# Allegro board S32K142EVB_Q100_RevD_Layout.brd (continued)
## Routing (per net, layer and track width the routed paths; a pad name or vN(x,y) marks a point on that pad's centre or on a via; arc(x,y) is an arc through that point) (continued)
SDA_SWD_EN_B_R: length 3.1
  TOP w0.16: R49.1 37.17,38.52 v1(37.17,38.54) 37.17,38.54 37.17,38.55 36.6,39.13 R42.2 35.78,39.15 35.63,39.3 U9.1
SDA_SWD_EN_R: length 3.7
  TOP w0.16: U10.5 R52.2 31.03,38.13 R51.1 32.03,38.13 R47.2
SDA_SWD_OE: length 2.5
  TOP w0.16: U9.4 34.05,40 33.9,40.15 R35.1 R38.1
SDA_SWD_OE_B: length 19.5
  TOP w0.16: v1(35.85,40.73) 35.59,41 35.59,41.44 R32.2 ; v1(25.27,37.82) 24.3,37.82 23.87,37.39 21.49,37.39 U8.20
  BOTTOM w0.16: v1(25.27,37.82) 26.89,36.19 32.87,36.19 35.12,38.44 35.12,38.89 35.42,39.19 35.42,40.3 v1(35.85,40.73)
SDA_SWD_OE_B_R: length 3.5
  TOP w0.16: U9.3 35.64,40 35.79,40.15 R39.1 R32.1 v1(36.6,42.23)
SDA_SWD_OE_R: length 3.7
  TOP w0.16: U7.5 30.4,41.16 30.43,41.19 R30.2 R31.1 31.99,41.16 R35.2
SDA_USB_CONN_DN: length 13.3
  TOP w0.145: J7.2 4.65,43.37 4.83,43.55 7.56,43.55 7.94,43.17 7.94,43.11 ; 7.94,43.11 8.34,43.52 12.57,43.52 13.41,44.37 15.33,44.37 15.73,43.97 R25.1 ; 7.94,43.11 D19.2
SDA_USB_CONN_DP: length 13.6
  TOP w0.145: 7.92,44.3 7.46,43.85 4.85,43.85 4.67,44.02 J7.3 ; 7.92,44.3 D18.2 ; 7.92,44.3 7.92,44.29 8.39,43.82 12.44,43.82 13.29,44.66 15.45,44.66 15.94,44.18 R21.1
SDA_USB_DN: length 2.1
  TOP w0.145: U8.4 17.65,41.94 17.65,42.08 17.08,42.65 R25.2
SDA_USB_DP: length 2.1
  TOP w0.145: U8.3 17.99,42.31 17.84,42.31 17.29,42.86 17.29,42.86 17.25,42.9 R21.2
SDA_USB_P5V_SENSE: length 4.6
  TOP w0.16: v1(23.98,45.22) R14.2 22.79,44.04 22.79,44.04 R20.1 21.47,42.72 U8.30
SDA_USBSHIELD: length 9.3
  TOP w0.16: 6.21,40.76 L2.1 5.62,40.27
  TOP w1.016: J7.9 J7.8 J7.10
SDA_VOUT33: length 5.9
  TOP w0.254: C9.1 15.71,41.97 16.91,41.97 U8.5
  TOP w0.508: C9.1 15.18,41.44 13.8,41.44 13.55,41.69 R627.1
SDA_XTAL: length 5.3
  TOP w0.16: U8.18 20.95,36.51 22.61,36.51 C20.1 23.41,35.71 23.41,35.3 Y1.1
SW1_RST_B: length 14.2
  TOP w0.16: C1.1 v1(10.7,53.19) 11.15,53.63 SW5.2 SW5.4
  L3_MIX w0.16: v1(10.7,53.19) 10.7,51.79 J104.2
SWD_CLK_TGTMCU_BUF: length 1.5
  TOP w0.16: U10.4 29.34,37.23 29.55,37.01 R626.2
SWD_DIO_TGTMCU_BUF: length 11.6
  TOP w0.16: U7.4 v1(30.02,40.66) ; R625.2 31,47.92 v1(30.44,47.35) U2.2
  BOTTOM w0.16: v1(30.02,40.66) 30.78,40.66 32.05,41.94 32.05,45.74 v1(30.44,47.35)
TC_EXTAL_TP: length 2.2
  TOP w0.16: TP11.1 15.72,37.97 16.09,38.34 16.39,38.34 U8.10
TC_SDA_USB_ID_TP: length 2.2
  TOP w0.16: J7.4 5.88,44.67 TP6.1
TC_XTAL_TP: length 3
  TOP w0.16: U8.9 16.19,38.85 15.83,38.85 TP10.1
TP_2102_A: length 2.5
  TOP w0.16: U1.3 R607.2 7.71,53.43 v1(7.74,53.46)
TP_2102_B: length 1.6
  TOP w0.203: U1.6 7.31,49.22 7.2,49.11 R608.2
UART1_RX_TGTMCU_BUF: length 4.9
  TOP w0.16: R24.1 v1(32.98,43.47) 32.66,43.8 30.44,43.8 30.29,43.94 U4.4
UART1_RX_TGTMCU_R: length 8.8
  TOP w0.16: U8.25 22.89,40.6 23.67,40.6 23.84,40.42 25.39,40.42 v1(25.86,40.9) ; v1(27.02,43.73) 27.83,43.73 28.04,43.94 U4.3
  BOTTOM w0.16: v1(27.02,43.73) 27.02,42.06 v1(25.86,40.9)
UART1_TX_TGTMCU_BUF: length 3.2
  TOP w0.16: R18.1 32.44,46.65 32.26,46.83 v1(31.84,46.83) U2.1
UART1_TX_TGTMCU_R: length 10.9
  TOP w0.16: v1(27.12,44.65) 27.65,45.18 27.65,47.12 27.88,47.35 U2.6 ; U8.24 v1(23.29,40.08)
  BOTTOM w0.16: v1(27.12,44.65) 26.34,43.87 26.34,43.14 v1(23.29,40.08)
UART_RX: length 53.1
  TOP w0.16: R161.1 v1(84.29,44.36) ; R24.2 v1(34.89,44.49)
  BOTTOM w0.16: v1(34.89,44.49) 48.98,44.49 51.02,46.52 51.05,46.52 51.13,46.6 72.78,46.6 73.11,46.27 82.38,46.27 v1(84.29,44.36)
UART_TX: length 55.6
  TOP w0.16: R162.1 v1(85.43,44.36) ; R18.2 v1(34.51,46.65)
  BOTTOM w0.16: v1(34.51,46.65) 35.27,46.65 36.86,45.06 48.67,45.06 50.38,46.77 50.79,46.77 50.88,46.86 50.91,46.86 50.99,46.94 72.92,46.94 73.21,46.65 83.78,46.65 85.43,45 v1(85.43,44.36)
V_TGTMCU: length 15.8
  TOP w0.203: v1(8.22,47.41) R608.1 8.22,49.11 8.11,49.22 U1.8
  TOP w0.254: U10.6 29.8,38.62 29.88,38.7 v1(30.05,38.7) ; v1(30.04,41.89) 29.81,41.66 U7.6 ; U2.8 29.05,46.31 v1(29.34,46.01) U4.6 ; 2.99,49.63 C4.1 ; 2.98,50.98 R2.2 2.47,50.47 ; 3.5,51.1 R4.1 2.99,50.59 ; 1.49,50.47 C2.1 0.98,50.98 ; C8.1 v1(30.09,42.77)
  TOP w0.762: v1(38.48,42.57) v1(39.52,42.57) 39.52,39.41 38.86,38.76 SH1.1
  vias: v1(1.85,50.09) v1(2.77,50.09)
VSUP: length 34.6
  TOP w0.254: U19.14 v1(15.66,18.74)
  TOP w0.381: TP508.1 35.35,14.56 ; TP508.1 35.35,15.49 ; TP508.1 34.42,14.56 ; TP508.1 34.89,14.45 ; TP508.1 35.46,15.02 ; TP508.1 34.31,15.02 ; TP508.1 34.89,15.6 ; TP508.1 34.42,15.49 ; 34.47,18.33 C47.1 ; C47.1 34.59,18.16 ; C47.1 34.51,18.58 ; C47.1 34.77,18.04 ; C47.1 35.44,18.16 ; C47.1 35.01,18.07 ; 32.08,16.87 Q1.2 ; Q1.2 32.08,17.86 ; Q1.2 32.88,17.37 ; C546.1 36.67,18.58 ; C546.1 36.16,18.07 ; C546.1 36.58,18.16 ; C546.1 35.91,18.04 ; C546.1 35.73,18.16 ; C546.1 35.61,18.33 ; Q1.1 32.88,16.1 ; Q1.1 32.08,15.6 ; Q1.1 32.08,16.59 ; 32.08,18.14 Q1.3 32.88,18.64 ; 32.26,11.98 D9.C ; D9.C 33.15,10.73 ; D9.C 33.15,13.22 ; D9.C 34.04,11.98 ; 37.11,10.96 C128.1 ; C128.1 39.08,11.98 ; C128.1 35.14,11.98 ; C128.1 37.11,12.99
  TOP w0.61: D6.A 20.63,23.5 21.29,24.16 U21.7
  TOP w0.635: D6.A v1(17.99,23.5) ; R537.1 10.42,9.04 11.06,9.67 v1(11.06,9.95)
  vias: v1(32.09,13.88) v1(34.63,11.98)
VTRG_EN: length 4.6
  TOP w0.16: R69.2 R68.1 R70.2 v1(9.98,31.94) U11.3
VTRG_FAULT_B: length 16.3
  TOP w0.16: U11.4 11.22,35.53 R60.2 v1(12.67,35.53) ; v1(20.38,43.64) 20.38,43.04 U8.32
  BOTTOM w0.16: v1(12.67,35.53) 14.62,37.48 14.62,39.3 15.71,40.39 17.59,40.39 20.38,43.18 v1(20.38,43.64)
N20187731: length 2.1
  TOP w0.16: D11.A3 119.42,15.43 119.34,15.51 R95.1
N20187747: length 2.1
  TOP w0.16: R96.1 121.5,15.45 121.52,15.43 D11.A2
N20224636: length 9.7
  TOP w0.16: R597.1 C5.1 119.78,46.27 119.81,46.24 R13.2 119.08,44.49 117.82,44.49 TP5.1
N20296072: length 11
  TOP w0.16: TP532.1 122.39,38.82 122.43,38.78 SW2.1 SW2.3 R44.1 119.72,32.55 R596.1
N20296289: length 10.8
  TOP w0.16: SW3.1 SW3.3 ; SW3.1 122.43,26.96 122.39,27 TP531.1 ; SW3.1 R74.1 119.71,25.82 R595.1
N20296614: length 2.1
  TOP w0.16: R97.1 123.66,15.47 123.62,15.43 D11.A1
N20337791: length 7.2
  TOP w0.16: R662.2 R122.2 70.37,39.61 U35.98
N20337946: length 51.4
  TOP w0.16: R165.2 v1(82.99,44.37) ; v1(73.49,14.01) 73.49,14.85 R166.2
  L3_MIX w0.16: J5.3 73.11,8.17 73.11,12.61 73.49,12.99 v1(73.49,14.01) ; v1(82.99,44.37) 82.32,43.71 82.32,35.18 83.03,34.48 83.03,16.55 v1(82,15.53)
  BOTTOM w0.16: v1(82,15.53) 81.88,15.66 75.15,15.66 v1(73.49,14.01)
N20338052: length 6.6
  TOP w0.16: U35.92 73.37,37.88 72.86,38.39 72.86,39.41 73.25,39.79 R123.2 R663.2
N20338949: length 53.8
  TOP w0.16: v1(71.34,14.01) 71.97,14.65 R168.2 ; J5.1 v1(71.69,5.12) ; R167.2 v1(81.31,44.27)
  L3_MIX w0.16: v1(71.34,14.01) 71.34,12.96 71.25,12.88 71.25,6.86 71.69,6.43 v1(71.69,5.12) ; v1(81.31,44.27) 81.37,44.21 81.37,41.69 81.64,41.42 81.64,34.9 82.32,34.23 82.32,18.76 80.86,17.31 v1(80.86,15.15)
  BOTTOM w0.16: v1(80.86,15.15) 80.78,15.23 75.61,15.23 73.87,13.5 71.85,13.5 v1(71.34,14.01)
N20339030: length 5.4
  TOP w0.16: U35.66 84.81,30.66 86.07,31.92 R124.2 R637.2
N20339144: length 8.1
  TOP w0.16: U35.65 85.2,30.16 86.34,31.3 88.88,31.3 89.5,31.92 89.5,32.93
N20339274: length 4.9
  TOP w0.16: R640.2 R126.2 86.32,29.76 86.22,29.66 U35.64
N20339954: length 6.3
  TOP w0.16: U35.95 71.87,41.08 72.22,41.44 R633.2 R128.2
N20341657: length 93.8
  TOP w0.16: R133.1 88.98,16.43 v1(89.62,15.79) ; R132.1 v1(65.24,13.89)
  L3_MIX w0.16: J1.13 48.22,51.22 49.02,50.42 49.02,39.7 48.13,38.81 48.13,36.31 48.54,35.9 51.22,35.9 52.67,34.46 52.67,28.5 50.38,26.22 50.38,24.88 49.1,23.59 48.39,23.59 46.94,22.14 46.94,16.18 48.86,14.26 v1(48.86,12.23)
  BOTTOM w0.16: v1(89.62,15.79) 89.37,16.04 72.61,16.04 70.46,13.89 v1(65.24,13.89) 61.04,13.89 60.54,14.39 59.14,14.39 57.49,12.74 57.46,12.74 57.43,12.7 49.33,12.7 v1(48.86,12.23)
N20341806: length 94.8
  TOP w0.16: v1(62.19,13.37) 62.15,13.41 R135.1 ; v1(88.69,13.72) R134.1
  L3_MIX w0.16: v1(44.41,10.96) 45.08,11.63 45.08,24.59 48.47,27.97 48.47,32.05 47.52,33 47.52,39.2 47.79,39.47 47.79,49.61 45.68,51.73 J1.15
  BOTTOM w0.16: v1(88.69,13.72) 88.48,13.92 86.26,13.92 84.87,12.53 78.93,12.53 78.73,12.74 69.19,12.74 68.68,12.23 66.93,12.23 66.16,13 65.28,13 65.15,12.87 62.69,12.87 v1(62.19,13.37) 61.73,13.37 61.72,13.37 58.63,13.37 57.37,12.1 49.38,12.1 49.05,11.77 48.67,11.77 48.06,12.37 45.83,12.37 v1(44.41,10.96)
N20342040: length 89.3
  TOP w0.16: v1(91.27,37.12) R539.2 R647.2 ; R567.2 v1(60.54,39.28)
  L3_MIX w0.16: v1(60.03,47.66) 60.03,39.79 v1(60.54,39.28)
  BOTTOM w0.16: v1(60.54,39.28) 60.67,39.15 63.33,39.15 64.94,37.55 84.45,37.55 84.88,37.12 86.96,37.12 88.48,35.6 91.53,35.6 91.78,35.85 91.78,36.61 v1(91.27,37.12) ; J2.19 21.93,50.2 38.44,50.2 39.46,49.19 51.9,49.19 53.17,47.92 59.78,47.92 v1(60.03,47.66)
N20342083: length 83.1
  TOP w0.16: R648.2 89.2,37.96 89.2,37.58 v1(88.73,37.12) R540.2 ; R568.2 v1(63.08,40.93)
  L3_MIX w0.16: v1(63.08,40.93) 63.08,41.82 62.57,42.33 62.57,47.54 v1(63.08,48.04)
  BOTTOM w0.16: J2.17 24.14,50.54 38.58,50.54 39.6,49.52 52.04,49.52 53.27,48.3 62.83,48.3 v1(63.08,48.04) ; v1(88.73,37.12) 87.72,38.14 85.93,38.14 84.87,39.19 77.87,39.19 77.37,39.7 69.57,39.7 69.31,39.96 69.31,40.38 69.01,40.68 68.58,40.68 68.28,40.38 68.28,39.96 68.02,39.7 64.7,39.7 63.46,40.93 v1(63.08,40.93)
N20342455: length 10.8
  TOP w0.16: U35.8 66.77,31.66 65.57,32.85 65.57,36.66 65.24,37 R659.1 R136.1
N20342663: length 6.8
  TOP w0.16: R137.1 R658.1 65.24,35.15 65.24,32.68 66.76,31.16 U35.9
N20344687: length 94.2
  TOP w0.16: R541.1 v1(91.27,36.11) ; J4.11 63.46,9.44 64.1,10.07 68.35,10.07 68.73,9.69 76.67,9.69 v1(76.92,9.94) ; R146.2 v1(77.43,14.14) ; R543.1 v1(60.54,40.3)
  L3_MIX w0.16: v1(91.27,15.79) 91.27,16.42 90.35,17.35 90.35,19.11 90.94,19.71 90.94,29.44 90.81,29.57 90.81,30.79 90.51,31.09 90.51,35.34 v1(91.27,36.11) ; v1(77.43,14.14) 76.92,13.63 v1(76.92,9.94)
  BOTTOM w0.16: v1(91.27,15.79) 89.75,14.26 84.94,14.26 84.81,14.14 v1(77.43,14.14) ; v1(91.27,36.11) 90.77,36.61 88.42,36.61 87.24,37.8 85.79,37.8 84.73,38.85 77.73,38.85 77.23,39.36 64.4,39.36 63.33,40.42 62.57,40.42 62.45,40.3 v1(60.54,40.3)
N20344693: length 79.5
  TOP w0.16: R542.1 v1(88.73,36.11) ; R147.2 v1(88.61,25.06) ; R544.1 v1(63.08,39.92)
  L3_MIX w0.16: v1(88.61,25.06) 88.69,25.14 88.69,26.21 87.8,27.1 87.8,35.17 v1(88.73,36.11) ; J4.9 60.92,14.9 62.06,16.04 62.06,16.8 60.25,18.62 60.25,24.25 60.72,24.71 61.51,24.71 61.89,25.09 61.89,38.73 v1(63.08,39.92)
  BOTTOM w0.16: v1(88.73,36.11) 88.45,36.11 87.1,37.46 85.02,37.46 84.55,37.93 84.35,37.93 83.89,38.39 77.72,38.39 77.09,39.02 74.65,39.02 74.07,38.44 73.68,38.44 73.1,39.02 64.26,39.02 63.36,39.92 v1(63.08,39.92)
N20349379: length 9
  TOP w0.16: R161.2 R630.2 83.91,40.81 82.95,40.81 81.55,39.41 80.2,39.41 78.87,38.08 U35.81
N20349445: length 10
  TOP w0.16: R162.2 R632.2 84.81,40.57 84.81,39.95 84.51,39.65 82.27,39.65 81.69,39.07 80.4,39.07 79.37,38.04 U35.80
N20351631: length 5.9
  TOP w0.16: U35.46 79.37,19.18 79.48,19.07 79.48,16.57 R164.2 R629.2
N20408163: length 3.3
  TOP w0.16: U15.3 35.7,32.71 35.67,32.68 R170.2 R169.2
  TOP w0.203: TP540.1 R169.2
N20408770: length 1.6
  TOP w0.16: C59.1 40.06,32.71 40.06,32.71 U15.4
N20424711: length 6.8
  TOP w0.16: U35.22 66.62,24.66 63.84,21.88 R653.1 R154.1
N20424784: length 6.2
  TOP w0.16: U35.21 66.36,25.16 65.12,23.91 R655.1 R155.1
N20424902: length 9.1
  TOP w0.16: U35.4 68.58,33.66 v1(68.92,33.31) ; R656.1 R156.1 v1(68.03,38.38)
  L3_MIX w0.16: v1(68.03,38.38) 68.03,38.01 69.07,36.97 69.07,34.82 69.43,34.46 69.43,33.82 v1(68.92,33.31)
N20428524: length 7.6
  TOP w0.16: 89.5,30.77 89.5,29.76 88.9,29.16 U35.63
N20428906: length 6.7
  TOP w0.16: U35.96 71.37,40.9 R634.2 R127.2
N20447644: length 40.6
  TOP w0.16: J1.1 64.6,52.24 68.8,52.24 69.08,51.95 81.78,51.95 83.38,50.35 83.38,48.57 85.05,46.9 85.94,46.9 v1(89.37,43.47) ; R644.2 v1(88.73,35.09)
  L3_MIX w0.16: v1(89.37,43.47) 89.08,43.18 89.08,42.25 89.2,42.14 89.2,35.55 v1(88.73,35.09)
N20447648: length 44.1
  TOP w0.16: v1(89.88,42.58) 89.12,42.58 85.81,45.89 84.92,45.89 82.77,48.04 82.77,50.08 81.62,51.22 68.67,51.22 68.29,51.6 62.7,51.6 J1.3 ; R643.2 v1(91.27,35.09)
  L3_MIX w0.16: v1(91.27,35.09) 91.74,35.55 91.74,36.3 91.47,36.57 90.94,36.57 89.88,37.63 v1(89.88,42.58)
N20483325: length 51.4
  TOP w0.16: R81.2 61.65,24.93 v1(61.07,25.51)
  L3_MIX w0.16: v1(61.07,25.51) 60.49,25.51 59.52,24.55 59.52,12.99 v1(58.89,12.36)
  BOTTOM w0.16: v1(58.89,12.36) 58.13,12.36 57.54,11.77 51.57,11.77 51.56,11.76 51.44,11.76 47.29,7.61 31.4,7.61 29.3,5.51 29.3,3.98 J3.2
N20483330: length 51
  TOP w0.16: R90.2 v1(60.92,27.98)
  L3_MIX w0.16: v1(60.92,27.98) 59.19,26.24 59.19,13.42 58.25,12.48 v1(58.25,11.72)
  BOTTOM w0.16: v1(58.25,11.72) 57.96,11.43 51.74,11.43 51.73,11.42 51.58,11.42 47.43,7.27 33.46,7.27 31.71,5.53 31.71,3.98 30.44,2.71 J3.4
N20483362: length 70.7
  TOP w0.16: R545.2 v1(75.27,43.22)
  L3_MIX w0.16: v1(75.4,12.28) 75.53,12.4 75.53,17.69 76.3,18.46 76.3,31.29 77.26,32.26 77.26,39.19 75.27,41.19 v1(75.27,43.22)
  BOTTOM w0.16: J3.14 44.54,3.98 44.54,5.51 45.29,6.26 47.87,6.26 52.02,10.41 58.79,10.41 59.05,10.67 62.86,10.67 63.03,10.5 71.76,10.5 72.86,11.6 74.72,11.6 v1(75.4,12.28)
N20483368: length 56.3
  TOP w0.16: R546.2 v1(64.1,43.09)
  L3_MIX w0.16: v1(62.57,10.2) 62.57,12.48 63.97,13.88 63.97,16.66 63.89,16.74 63.89,24.5 63.08,25.31 63.08,32.13 64.9,33.95 64.9,42.29 v1(64.1,43.09)
  BOTTOM w0.16: J3.16 46.77,3.66 46.77,4.68 52.16,10.07 58.93,10.07 59.05,10.2 v1(62.57,10.2)
N20484569: length 14.4
  TOP w0.16: R664.2 63.97,14.26 65.05,13.18 65.68,13.18 66.26,12.61 v1(66.26,11.47)
  L3_MIX w0.16: v1(66.26,11.47) 66.26,10.07 66.13,9.94 66.13,7.91 67.46,6.58 67.46,3.66 J4.16
N20487643: length 4.3
  TOP w0.16: R533.2 C533.1 ; R533.2 v1(99.2,30.39) ; R533.2 R525.1
N20487701: length 2.6
  TOP w0.16: R527.1 SW8.1
N20487722: length 4.4
  TOP w0.16: v1(98.17,17.25) C535.1 R534.2 R528.1
N20492371: length 11.9
  TOP w0.16: R660.1 R529.1 62.91,18.67 65.45,18.67 68.92,22.14 68.92,23.88 68.65,24.16 U35.23
N20498073: length 24
  TOP w0.16: Q1.4 33.21,19.91 33.28,19.98 v1(33.74,19.98) ; v1(14.9,18.24) U19.15
  BOTTOM w0.16: v1(14.9,18.24) 17.38,18.24 20.34,21.2 20.65,21.2 20.7,21.25 21.13,21.25 21.43,20.95 21.43,20.88 22.33,19.98 v1(33.74,19.98)
N20502236: length 8.4
  TOP w0.16: R532.1 R661.1 65.24,37.63 65.91,36.96 65.91,33.02 66.78,32.16 U35.7
N20519466: length 3.5
  TOP w0.16: C536.1 14.66,18.96 TP544.1 U19.13
N20529258: length 5.3
  TOP w0.508: R80.2 R171.2 13.51,22.82 14.19,23.5 D6.C
N20532266: length 22
  TOP w0.254: 27.56,14.98 TP523.1 ; TP523.1 27.46,14.52 ; TP523.1 28.6,14.52 ; TP523.1 27.56,14.05 ; TP523.1 28.5,14.05 ; TP523.1 28.5,14.98 ; TP523.1 28.03,15.09
  TOP w0.305: 22.44,18.83 21.85,18.24 21.76,18.24 21.74,18.22 20.9,18.22 20.89,18.24 U19.6
  TOP w0.381: 22.88,19.52 R535.2 ; R535.2 24.79,19.52 ; R535.2 23.84,18.88 ; R535.2 22.88,18.88 ; R535.2 24.79,18.88
  TOP w0.635: 28.05,15.62 Q1.5 ; Q1.5 28.05,20.39 ; Q1.5 30.64,18 ; Q1.5 25.46,18
N20533540: length 2.6
  TOP w0.16: R172.1 SW7.1
N20537015: length 24.9
  TOP w0.16: v1(14.95,20.1) 15.41,20.1 15.77,19.74 U19.12 ; TP518.1 2.15,11.88 SW9.3 SW9.1 R537.2 9.65,12.32 C551.1 v1(9.61,13.36)
  L3_MIX w0.16: v1(14.95,20.1) 12.92,20.1 8.6,15.79 8.6,14.26 9.17,13.69 9.29,13.69 v1(9.61,13.36)
N20615858: length 2.7
  TOP w0.16: U26.6 39.35,25.84 R590.1 R612.2
N20615860: length 3
  TOP w0.16: R613.2 37.81,26.84 38.57,26.84 R589.1 U26.7
N20628442: length 2.4
  TOP w0.16: R616.2 43.65,24.93 R585.1 U32.7
N20629726: length 1.3
  TOP w0.16: U32.2 43.88,21.16 43.9,21.14 R577.2
N20726302: length 1.5
  TOP w0.16: R578.2 44.55,20.98 44.28,21.25 U32.3
N20726411: length 2.4
  TOP w0.16: U32.6 44.68,23.68 R586.1 R609.2
N20727622: length 6.1
  TOP w0.16: U32.5 45.55,22.52 v1(45.94,22.9)
  TOP w0.203: R562.2 42.38,24.04 v1(42.51,24.17)
  BOTTOM w0.203: v1(42.51,24.17) 42.51,23.69 43.29,22.9 v1(45.94,22.9)
N20728836: length 9.8
  TOP w0.203: R98.1 5.93,16.42 5.17,17.18 5.17,19.47 5.93,20.23 R92.2 8.56,20.23 8.94,19.85 C40.1
N20751108: length 1.4
  TOP w0.16: U33.5 R571.2
N20751111: length 2.4
  TOP w0.16: U33.7 R587.1
  TOP w0.203: R587.1 49.24,24.93 R610.2
N20751112: length 2.4
  TOP w0.16: R588.1 50.27,23.68 U33.6
  TOP w0.203: R588.1 R611.2
N20754157: length 1.4
  TOP w0.16: R572.2 40.6,24.68 U26.5
N20757133: length 2.1
  TOP w0.16: U34.7 R591.1
  TOP w0.203: R591.1 R615.2
N20757185: length 2.4
  TOP w0.16: R592.1 39.6,20 U34.6
  TOP w0.203: R592.1 R614.2
N20757257: length 1.2
  TOP w0.16: R576.2 U34.5
N20757373: length 2.7
  TOP w0.16: U33.2 49.47,21.28 49.49,21.26 R579.2 47.97,20.74
N20757398: length 2.5
  TOP w0.16: U33.3 49.87,21.37 R580.2
  TOP w0.203: R580.2 50.63,20.61 R618.2
N20757820: length 3.3
  TOP w0.203: U26.2 38.55,23.64 38.41,23.5 37.34,23.5 R619.2 36.92,23.03 R581.2
N20757845: length 4
  TOP w0.203: U26.3 38.95,23.03 R582.2 40.09,22.9 40.6,23.4 40.85,23.4 R620.2
N20758005: length 2.7
  TOP w0.16: R583.2 38.8,17.42 U34.2
  TOP w0.203: R621.2 37.68,17.82 R583.2
N20758031: length 2.6
  TOP w0.16: R622.2 40.2,17.18 40.08,17.06 R584.2 39.2,17.31 U34.3
N20759089: length 1.4
  TOP w0.457: R56.2 D3.A
N20788275: length 3.2
  TOP w0.16: Q6.1 115.5,3.08 115.49,3.09 R599.1 R598.2 TPAD93.1
N20788431: length 3.2
  TOP w0.16: TPAD96.1 R601.2 R600.1 115.42,5.37 115.43,5.36 Q7.1
N20788562: length 3.6
  TOP w0.16: TPAD98.1 116.04,8.72 116.03,8.71 Q8.1 115.43,7.9 115.42,7.91 R602.1 R603.2
N20797138: length 3.7
  TOP w0.457: TPAD100.1 48.35,16.27 48.34,16.26 Q9.1 47.21,15.4 47.21,15.41
  TOP w0.635: TPAD100.1 R604.2
N20798434: length 1.8
  TOP w0.457: D3.C 49.63,14.38 Q9.3
N20799004: length 4.1
  TOP w0.635: R606.1 v1(5.93,18.2)
  L3_MIX w0.635: v1(5.93,18.2) 5.23,18.2 5.19,18.16 J13.3
N20829527: length 2.1
  TOP w0.635: U15.1 36.66,34.61 37.3,35.25 R624.2
N20859178: length 8
  TOP w0.16: R131.2 66.26,16.55 R635.2 68.24,19.34 69.68,19.34 70.87,20.53 U35.29
N20859231: length 8.1
  TOP w0.16: R636.2 R130.2 68.54,17.93 68.33,18.14 68.33,18.52 68.82,19 69.82,19 71.37,20.55 U35.30
N20864354: length 5.8
  TOP w0.16: R649.1 R650.1 71.46,18.07 71.46,18.45 72.37,19.36 U35.32
N20864532: length 6.1
  TOP w0.16: R651.1 R652.1 70.18,17.93 70.18,18.82 71.87,20.51 U35.31
N20866143: length 9.1
  TOP w0.16: U35.78 80.37,37.9 80.86,38.39 82,38.39 82.58,38.97 84.79,38.97 84.97,39.15 R666.2 R665.2
N20878661: length 6.3
  TOP w0.279: 66.64,29.66 66.38,29.4
  TOP w0.305: U35.12 66.64,29.66
  TOP w0.508: R569.1 63.59,29.25 TP545.1 R628.2 65.73,28.74 66.38,29.4
N20881189: length 5
  TOP w0.16: R667.2 R670.2 84.8,24.04 84.18,24.66 U35.54
N20881219: length 5.9
  TOP w0.16: U35.53 84.18,24.16 85.24,23.09 85.24,22.83 86.32,21.76 R669.2 R668.2
N207179701: length 1
  TOP w0.635: C544.2 C545.1
N207665286: length 2.3
  TOP w0.16: TP542.1 54.87,43.09 54.86,43.1 J14.7
N207665288: length 2.3
  TOP w0.16: J14.9 54.86,44.37 54.87,44.36 TP543.1

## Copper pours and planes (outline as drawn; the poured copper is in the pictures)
P3V3 on TOP: 38.97,26.63 38.97,26.65 38.38,27.24 38.38,35.34 45.55,35.34 45.55,27.1 45.09,26.63
P3V3 on L3_MIX: 42.13,33.3 42.13,29.32 39.97,27.16 39.97,20.49 36.8,17.32 36.8,4.03 32.57,4.03 32.57,22.99 36.03,26.45 36.03,27.2
P3V3_SDA on TOP: 31.33,37.21 31.33,35.22 30.44,34.33 30.06,34.33 30.06,37.25 31.29,37.25
P3V3_SDA on TOP: 8.44,51.41 9.73,51.41 10.09,51.05 10.09,49.5 9.33,49.5 8.44,50.4
P3V3_SDA on BOTTOM: 32.6,37.38 32.6,36.36 28.54,36.36 28.3,36.6 28.3,38.09 28.05,38.34 27.28,38.34 27.09,38.53 27.09,39.62 27.57,40.1 27.57,42.13 28.25,42.82 28.25,45.07 26.22,45.07 24.62,46.66 21.68,46.66 19.44,48.9 17.24,48.9 17.24,46.93 19.85,44.32 19.85,43.08 19.22,42.46 16.84,44.84 14.48,44.84 13.48,43.84 13.48,37.34 11.86,35.72 11.86,31.77 12.24,31.39 13.58,31.39 13.58,33.98 16.27,36.67 16.27,38.06 16.44,38.23 16.92,38.23 16.92,36.23 14.57,33.88 14.57,28.39 19.42,28.39 19.42,27.16 18.7,26.45 11.78,26.45 10.59,27.64 10.59,47.79 9.23,47.79 8.22,48.81 7.96,48.81 7.71,49.06 7.71,50.13 7.58,50.25 5.95,50.25 4.72,51.49 4.72,52.73 5.88,53.89 8.85,53.89 10.72,52.02 18.16,52.02 20.99,49.19 25.53,49.19 29.03,45.69 30.44,45.69 30.44,44.44 30.42,44.43 30.42,44.36 31.38,43.4 31.38,42.64 31.09,42.35 28.87,42.35 28.87,40 28.92,39.96 31.36,39.96 34.29,42.89 37.86,42.89 37.86,41.58 35.4,41.58 34.63,40.82 34.63,39.41
P5V0 on BOTTOM: 23.85,34.37 28.15,34.37 28.53,33.99 42.69,33.99 42.69,26.33 41.81,25.44 38.95,25.44 38.06,26.33 30.47,26.33 30.47,31.07 26.49,31.07 26.49,26.33 23.85,26.33 ; 1 cut-out
P5V0 on L3_MIX: 43.47,5.07 42.44,4.04 37.05,4.04 37.05,15.86 40.73,19.55 40.73,24.3 40.35,24.68 40.35,26.91 42.69,29.25 43.9,29.25 43.9,14.59 44.79,13.7 44.79,8.8 43.47,7.48
P5V0 on L3_MIX: 27.14,34.33 27.14,32.42 31.08,28.49 34.89,28.49 35.39,28.99 35.39,32.93 37.93,35.47 37.93,36.36 37.55,36.74 35.52,36.74 34.38,35.6 28.41,35.6
P5V_SBC on TOP: 43.4,24.04 43.4,21.63 42.56,20.79 37.02,20.79 36.37,21.45 33.22,21.45 33.22,25.92 37.89,25.92 37.89,22.77 39.84,22.77 42,24.93 42.51,24.93 ; 2 cut-outs
P5V_SBC on BOTTOM: 50.51,21.5 51.46,20.55 52.35,20.55 52.54,20.74 52.54,23.76 50.36,23.76 50.03,23.44 38.57,23.44 36.16,25.86 36.16,26.14 30.3,26.14 30.3,30.89 26.69,30.89 26.69,22.87 31.3,22.87 31.84,23.41 37.3,23.41 38.7,22.01 42.13,22.01 42.63,21.5 ; 1 cut-out
P5V_SDA on TOP: 22.29,44.5 23.47,45.69 22.26,46.9 6.97,46.9 6.97,45.62 17.57,45.62 17.93,45.99 19.59,45.99 19.95,45.62 21.17,45.62
P5V_SDA on BOTTOM: 6.91,45.99 6.91,28.58 9.61,28.58 9.61,46.33 7.24,46.33
VBATT on TOP: 22.08,6.67 21.55,7.2 21.55,12.74 24.35,12.74 25.36,13.75 30.31,13.75 30.57,13.5 30.57,10.07 30.06,9.56 26.5,9.56 26.5,8.93 26,8.42 26,7.02 26.38,6.64 28.66,6.64 29.3,6.01 29.3,4.61 29.04,4.36 26.66,4.36 24.35,6.67
VDD on TOP: 48.7,25.93 45.76,25.93 45.76,35.84 41.36,35.84 41.36,37 41.24,37.12 39.81,37.12 39.81,38.45 40.38,39.02 44.03,39.02 45.3,40.29 45.3,46.01 45.81,46.52 47.97,46.52 48.6,45.89 48.6,38.14 48.98,37.76 50.63,37.76 52.51,39.64 54.83,39.64 54.83,32.8 50.38,28.36 48.7,28.36 ; 1 cut-out
VDD on BOTTOM: 70.76,4.08 71.97,4.08 74.49,1.56 103.97,1.56 106.01,3.59 115.79,3.59 123.15,10.96 123.15,49.82 119.09,53.89 112.1,53.89 111.34,54.65 111.34,57.32 118.05,57.32 124.56,50.8 124.56,9.61 115.51,0.56 69.72,0.56 69.72,3.04
VDD on L3_MIX: 71.7,3.86 71.7,0.56 26.38,0.56 25.9,1.05 25.9,8.08 26.05,8.23 26.05,19.52 35.52,28.99 35.52,32.55 41.45,38.48 44.34,38.48 44.34,36.74 44.03,36.74 43.65,36.36 43.65,35.09 35.9,27.34 35.9,26.45 32.11,22.66 32.11,3.86
VDD_MCU on TOP: 58.25,36.11 58.25,34.84 58.76,34.33 59.91,34.33 60.67,33.57 60.67,32.42 63.97,32.42 64.99,31.41 65.37,31.41 66.26,30.52 68.54,30.52 69.38,29.68 75.6,29.68 75.6,31.21 69.22,31.21 68.82,30.81 66.73,30.81 65.24,32.3 65.24,33.57 62.57,33.57 60.03,36.11
VDD_MCU on L3_MIX: 75.31,38.77 75.31,34.93 74.55,34.18 74.55,19.81 74.89,19.47 75.8,19.47 75.8,26.05 75.6,26.25 75.6,33.29 76.25,33.94 76.25,38.77
VDD_PERH on TOP: 51.02,15.28 51.02,12.48 56.35,12.48 56.35,15.28
VDD_PERH on BOTTOM: 79.97,57.19 79.97,54.78 80.73,54.01 100.8,54.01 104.61,50.2 116.55,50.2 118.58,48.17 118.58,11.47 114.26,7.15 108.04,7.15 105.88,9.31 99.78,9.31 96.1,5.63 82.51,5.63 82.13,5.25 82.13,2.45 82.77,1.82 103.72,1.82 105.75,3.85 115.79,3.85 122.77,10.83 122.77,49.57 118.83,53.51 109.82,53.51 106.01,57.32 80.1,57.32
VDDA on TOP: 66.13,30.39 66.13,29.88 64.73,29.88 64.73,30.39 64.22,30.9 59.91,30.9 58.38,29.38 57.62,29.38 57.62,32.42 55.84,34.2 55.84,39.54 58,39.54 58,34.96 58.64,34.33 59.65,34.33 60.54,33.44 60.54,32.3 63.84,32.3 64.86,31.28 65.24,31.28
(no net) on TOP: 8.9,0.52 2.98,2.97 0.53,8.89 0.52,40.98 0.84,40.98 0.84,42.44 0.52,42.44 0.52,45.61 0.84,45.61 0.84,47.07 0.52,47.07 0.52,49.54 2.97,55.46 8.89,57.91 116.87,57.91 122.79,55.46 125.25,49.53 125.25,8.89 122.79,2.96 116.87,0.51 ; 81 cut-outs
(no net) on BOTTOM: 125.25,8.89 122.79,2.96 116.87,0.51 8.93,0.52 3,2.98 0.55,8.9 0.52,49.52 2.96,55.45 8.89,57.91 116.87,57.91 122.79,55.46 125.25,49.53 ; 37 cut-outs
(no net) on L3_MIX: 125.25,8.89 122.79,2.96 116.87,0.51 8.9,0.52 2.99,2.98 0.55,8.9 0.52,49.54 2.97,55.46 8.89,57.91 116.87,57.91 122.79,55.46 125.25,49.53 ; 48 cut-outs
SDA_USBSHIELD on TOP (solid shape): 2.43,48.27 5.1,48.27 5.1,46.25 3.86,46.25 3.86,47.25 0.53,47.25 0.53,48.98 2.43,48.98
SDA_USBSHIELD on TOP (solid shape): 5.1,39.78 2.43,39.78 2.43,39.07 0.53,39.07 0.53,40.8 3.86,40.8 3.86,41.8 5.1,41.8
SDA_USBSHIELD on TOP: 5.01,39.78 6.6,39.78 6.6,40.84 6.59,40.85 4.97,40.85 4.93,40.81 4.93,39.86
V_TGTMCU on TOP: 0.83,51.31 3.57,51.31 3.77,51.11 3.77,49.76 3.45,49.43 1.64,49.43 0.83,50.24
V_TGTMCU on L3_MIX: 1.3,51.32 7.24,51.32 9.49,49.07 9.49,46.8 9.97,46.32 12.11,46.32 15.42,49.62 32.42,49.62 35.79,46.26 39.87,46.26 39.87,42.24 38.09,42.24 38.09,43.84 34.98,43.84 30.96,47.86 29.93,47.86 29.93,46.9 31.22,45.61 31.22,41.9 30.35,41.04 30.35,38.27 28.8,38.27 28.8,45.71 27.13,47.39 16.71,47.39 14.47,45.15 8.99,45.15 4.85,49.29 1.3,49.29
VSUP on TOP: 31.58,19.02 37.47,19.02 37.47,14.66 39.32,14.66 39.46,14.52 39.46,10.45 31.58,10.45
VSUP on BOTTOM: 18.66,24.27 18.66,21.95 16.1,21.95 16.1,18.52 13.8,18.52 13.8,14.56 35.78,14.56 35.78,11.98 35.01,11.21 30.44,11.21 29.3,12.36 13.69,12.36 12.39,11.06 12.39,9.6 10.85,9.6 10.73,9.72 10.73,12.4 11.88,13.56 11.88,24.27
N20532266 on TOP: 30.99,13.88 30.99,21.83 22.24,21.83 22.24,18.48 25.06,18.48 25.06,13.88

Small or netless copper shapes (teardrops, artwork), in the pictures only: 1 on L2_GND

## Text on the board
BOTTOM: 170-29701 REV D | 7 OF 9 | SECONDARY SIDE
Board Geometry/Soldermask Bottom: 8 OF 9 | SECONDARY SOLDERMASK
Ref Des/Silkscreen Bottom: GND | LIN | VBAT | CAN_HI | CAN_LO | VDD | OpenSDA | J3 | B6 | VIN | IOREF | B7 | E0 | RESET | 3.3V | E9 | 5V | C5 | C4 | A10 | A4 | J2 | J4 | E10/A3 | NC | E8/C11 | D4 | C7 | E3 | E11/A2 | C3/C10 | B12 | D3 | C6 | A14 | AREF | B0 | B11 | D5 | B17 | E7 | B1 | B10 | D12 | B14 | C13 | B2 | A6/E11/A2 | B9 | D11 | B15 | C12 | B3 | D10 | C0/E10/A3 | B8 | B16 | E8 | B4 | C14 | D0 | E2 | A3 | A17 | B5 | A11 | E6 | A2 | C3 | D16 | D14 | D15 | D13 | J1 | E4 | A9 | A8 | E5 | E12 | A12 | A13 | D17 | C9 | C8 | C16 | D8 | C17 | D9 | D2 | J5 | D1 | E16 | A15/D11 | J6 | E15 | A16/D10 | E14 | A1 | E13 | A0 | A7 | B13 | E1 | C1 | D7 | C2 | D6 | C15 | 9 OF 10 | SECONDARY SILKSCREEN
User.Comments: 1 OF 1 | TEST PROBE | 1/1 | 1
TOP: 4 OF 9 | PRIMARY SIDE
Board Geometry/Soldermask Top: 3 OF 9 | PRIMARY SOLDERMASK
Ref Des/Silkscreen Top: SBC_IO | LIN | VSUP | RESET | # | P5V0 | *** | * | ## | GND | SWD_DIO | P3V3 | VDD | SWD | ~ | VDD_PERH | A | VDD_MCU | POT | B | G | R | CAN | LO | HI | PWR IN (5-12V) | SDA | VBAT | ** | MCU | VDDA_MCU | X | XX | // | TOUCH ELECTRODES | 2 OF 9 | PRIMARY SILKSCREEN | S32K142EVB-Q100
L2_GND: 5 OF 9 | GROUND PLANE
L3_MIX: 6 OF 9 | MIXED SIGNAL
XSECTION_CHART: *  SURFACE - AIR 0 MIL | *  DIELECTRIC - DRY_FILM_MASK 3 MIL | L1: TOP CONDUCTOR - 1OZ_COPPER 1.44 MIL | *  DIELECTRIC - FR-4 8 MIL | L2: L2_GND PLANE - COPPER 1.2 MIL | *  DIELECTRIC - FR-4 34 MIL | L3: L3_MIX PLANE - COPPER 1.2 MIL | L4: BOTTOM CONDUCTOR - COPPER_1OZ 1.44 MIL | DESIGN CROSS SECTION CHART | ___________________________ | TOTAL THICKNESS 61.28 MIL | 1-4
DIMENSION: SCALE: NONE | 22. | Location           RefDes      Net 1                  Net 2 | (470.00 1680.00)   J105      SDA_RST_TGTMCU_J_B  &  SDA_RST_TGTMCU_B | (1213.10 1300.30)  SH1       V_TGTMCU            &  VDD | INTENTIONAL 5 SHORTS AT: | LAYER STACKUP | DETAIL A | 17 | X4 | 16 | 8 | PRIMARY DATUM | GRID ORIGIN
DISPLAY_TOP: 1 OF 9 | PASTEMASK TOP
User.5: 9 OF 9 | SECONDARY PASTEMASK
User.14: 04-26-17 | 09-22-17 | L.M. | B | D | SCHEMATIC CHANGED PER ECO72567 | SCHEMATIC CHANGED PER ECO75961
User.20: FIGURE | SIZE | 8.0 | 10.0 | 14.0 | 15.0 | 28.0 | 31.0 | 40.0 | 44.0 | 45.0 | 63.0 | 100.0 | 125.0 | 34.0x26.0 | 60.0x33.0 | 111.0x32.0 | 122.0x32.0 | DRILL CHART: TOP to BOTTOM | ALL UNITS ARE IN MILS | TOLERANCE | +0.0/-8.0 | +0.0/-10.0 | +2.0/-2.0 | +3.0/-3.0 | PLATED | NON-PLATED | QTY | 400 | 492 | 17 | 2 | 1 | 20 | 121 | 9 | 4 | 3
